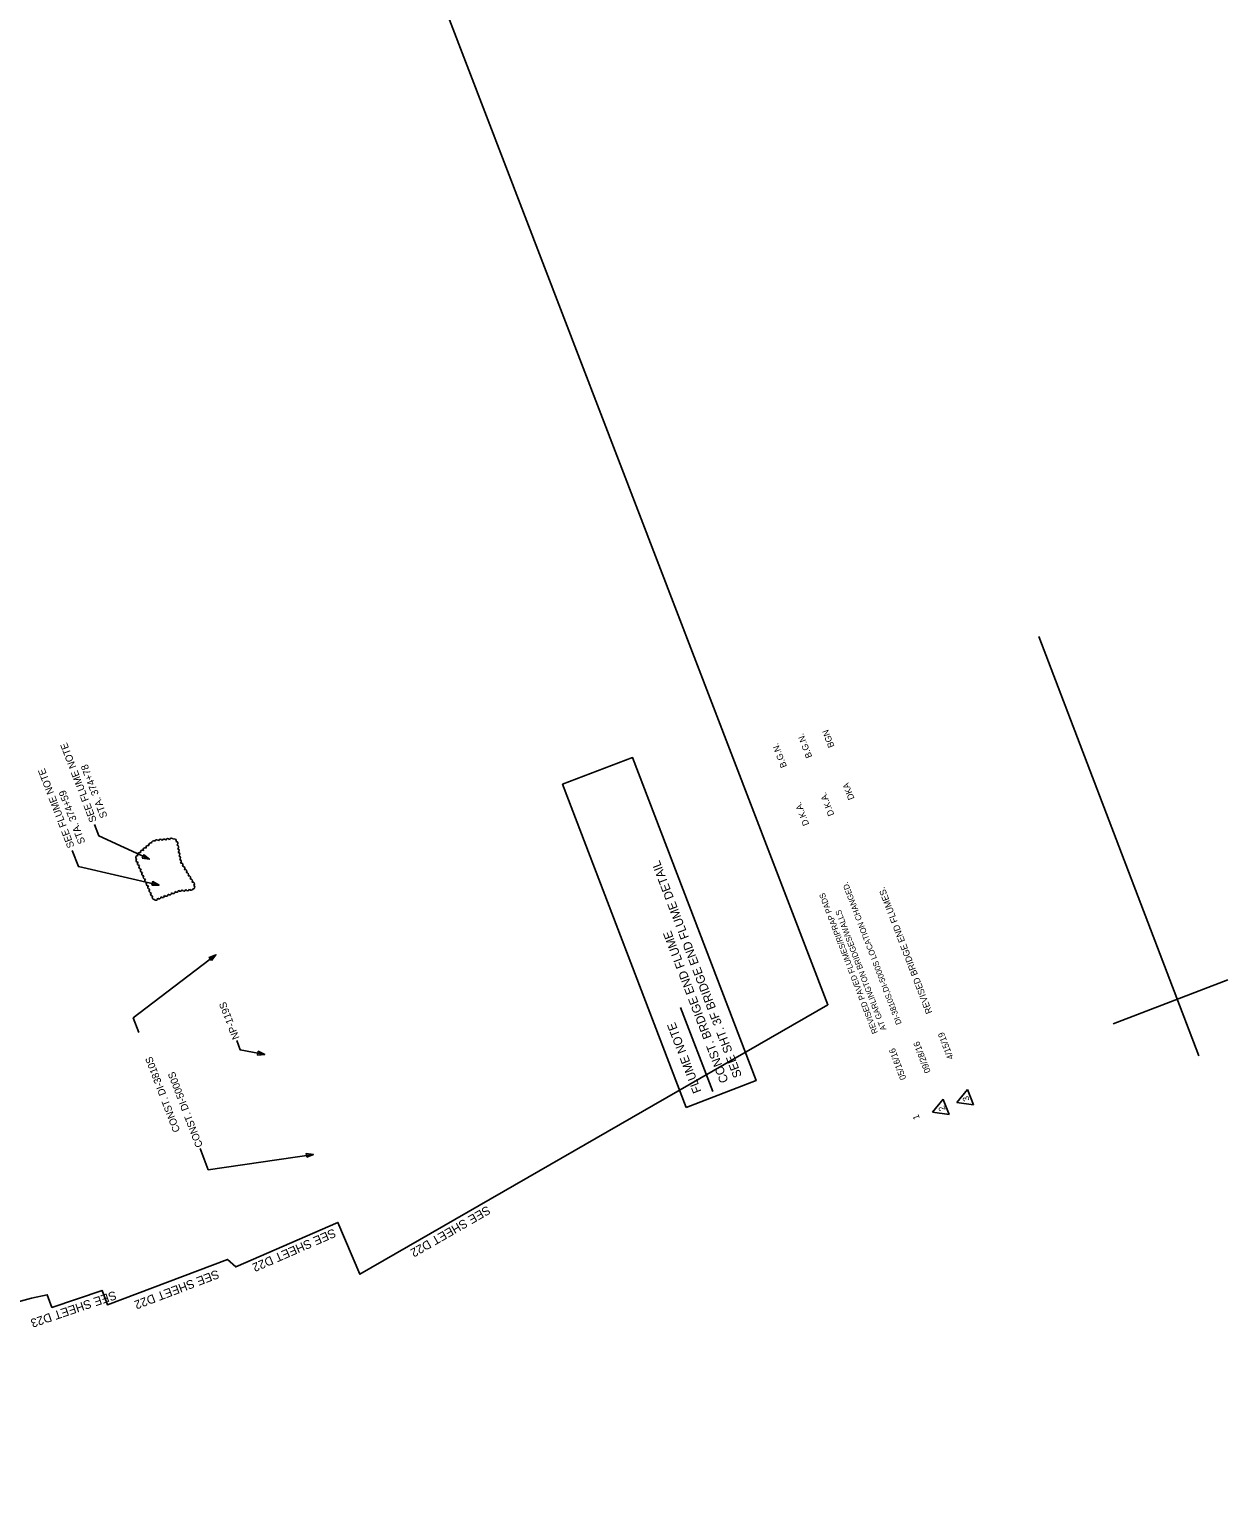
# Model space of a CAD drawing. Extents: x 1611058 to 1612754, y 1091411 to 1093437.
# Drawn here: x 1611925 to 1612754, y 1091411 to 1092422 of the extents above; entities that cross this region are included whole.
import ezdxf

# ---------------------------------------------------------------- set-up
doc = ezdxf.new("R2010")
doc.units = 0
for name, color, linetype in [('BR_CONCRETE', 7, 'Continuous'), ('North Arrow', 7, 'Continuous'), ('RD_HY_Area_XP-Post sub TXT', 7, 'Continuous'), ('RD_HY_Area_XP-Pre sub', 7, 'Continuous'), ('RD_HY_Misc', 7, 'Continuous')]:
    doc.layers.add(name, color=color, linetype=linetype)

msp = doc.modelspace()

# ---------------------------------------------------------------- linework, layer by layer
at = {"layer": 'BR_CONCRETE'}
msp.add_line((1612397.4, 1091687.5), (1612375.2, 1091745.7), dxfattribs=at)
for points in [[(1611969.8, 1091872.1), (1611972.7, 1091864.4), (1612007.7, 1091848.1)], [(1611954.4, 1091854.2), (1611958.6, 1091843.1), (1612014.4, 1091830.3)], [(1612000.5, 1091728.2), (1611996.6, 1091738.4), (1612053.7, 1091782.1)], [(1612068.1, 1091722.8), (1612070.5, 1091716.4), (1612087.5, 1091713.1)], [(1612042.8, 1091648), (1612048.4, 1091633.3), (1612121.2, 1091644)]]:
    msp.add_lwpolyline(points, dxfattribs=at)
for points in [[(1612002.8, 1091849), (1612007.7, 1091848.1), (1612003.9, 1091851.3)], [(1612009.5, 1091830.2), (1612014.4, 1091830.3), (1612010, 1091832.7)], [(1612050.7, 1091778.2), (1612053.7, 1091782.1), (1612049.1, 1091780.2)], [(1612082.5, 1091712.7), (1612087.5, 1091713.1), (1612083, 1091715.3)], [(1612116.6, 1091642.1), (1612121.2, 1091644), (1612116.2, 1091644.6)]]:
    msp.add_lwpolyline(points, close=True, dxfattribs=at)
for centre, start, end in [((1612006.7, 1091856.4), 59.0384, 204.0384), ((1612008.6, 1091858.1), 59.0384, 204.0384), ((1612010.6, 1091859.6), 47.5873, 192.5873), ((1612012.8, 1091860.3), 23.5735, 168.5735), ((1612015.3, 1091860.6), 23.5735, 168.5735), ((1612017.9, 1091860.8), 23.5735, 168.5735), ((1612020.4, 1091861.1), 23.5735, 168.5735), ((1612023, 1091861.4), 23.5735, 168.5735), ((1612025, 1091860.9), 343.5777, 128.5777), ((1612026.1, 1091859.2), 297.3546, 82.3546), ((1612026.6, 1091856.6), 297.3546, 82.3546), ((1611999.7, 1091849.5), 88.2114, 233.2114), ((1611999.8, 1091847.4), 131.0031, 276.0031), ((1612000.9, 1091851.4), 59.0384, 204.0384), ((1612002.9, 1091853.1), 59.0384, 204.0384), ((1612004.8, 1091854.8), 59.0384, 204.0384), ((1612027, 1091854.1), 297.3546, 82.3546), ((1612027.4, 1091851.6), 297.3546, 82.3546), ((1612027.9, 1091849.1), 297.3546, 82.3546), ((1612028.5, 1091846.6), 305.6611, 90.6611), ((1612000.8, 1091845.1), 131.0031, 276.0031), ((1612001.8, 1091842.7), 131.0031, 276.0031), ((1612002.8, 1091840.4), 131.0031, 276.0031), ((1612003.8, 1091838), 131.0031, 276.0031), ((1612029.6, 1091844.2), 318.5086, 103.5086), ((1612030.9, 1091842), 318.5086, 103.5086), ((1612032.2, 1091839.8), 318.5086, 103.5086), ((1612033.5, 1091837.6), 318.5086, 103.5086), ((1612004.8, 1091835.7), 131.0031, 276.0031), ((1612005.9, 1091833.4), 131.0031, 276.0031), ((1612006.9, 1091831), 131.0031, 276.0031), ((1612007.9, 1091828.7), 131.0031, 276.0031), ((1612034.1, 1091827.7), 202.4738, 347.4738), ((1612034.9, 1091835.4), 318.5086, 103.5086), ((1612036.6, 1091828), 202.4738, 347.4738), ((1612036.2, 1091833.2), 318.5086, 103.5086), ((1612037.5, 1091831.1), 318.5086, 103.5086), ((1612037.8, 1091829), 275.4894, 60.4894), ((1612008.9, 1091826.3), 131.0031, 276.0031), ((1612009.9, 1091824), 131.0031, 276.0031), ((1612011, 1091821.6), 131.0031, 276.0031), ((1612012.1, 1091821.1), 218.4145, 3.4145), ((1612014.5, 1091822.1), 218.4145, 3.4145), ((1612016.9, 1091823), 218.4145, 3.4145), ((1612019.3, 1091823.9), 218.4145, 3.4145), ((1612021.7, 1091824.8), 218.4145, 3.4145), ((1612024.1, 1091825.7), 218.4145, 3.4145), ((1612026.5, 1091826.6), 218.4145, 3.4145), ((1612029, 1091827.3), 204.5974, 349.5974), ((1612031.6, 1091827.5), 202.4738, 347.4738)]:
    msp.add_arc(centre, 1.34, start, end, dxfattribs=at)
at = {"layer": 'North Arrow'}
msp.add_lwpolyline([(1612379, 1091676.5), (1612293.6, 1091900), (1612342, 1091918.5), (1612427.4, 1091695)], close=True, dxfattribs=at)
at = {"layer": 'RD_HY_Area_XP-Pre sub'}
for p, q in [((1612622.9, 1092002.3), (1612733.7, 1091712.1)), ((1612753.7, 1091764.7), (1612674.3, 1091734.4)), ((1612573.7, 1091688.8), (1612566.3, 1091679.9)), ((1612577.8, 1091678.2), (1612573.7, 1091688.8)), ((1612556.8, 1091682.1), (1612549.4, 1091673.2)), ((1612556.9, 1091681.9), (1612556.8, 1091682.1)), ((1612560.9, 1091671.5), (1612556.9, 1091681.9)), ((1612566.3, 1091679.9), (1612577.8, 1091678.2)), ((1612549.4, 1091673.2), (1612560.9, 1091671.5))]:
    msp.add_line(p, q, dxfattribs=at)
at = {"layer": 'RD_HY_Misc'}
msp.add_lwpolyline([(1611114.1, 1092647.8), (1611496.9, 1091646.4), (1611649.2, 1091411.3), (1611823.9, 1091453.3), (1611846.4, 1091519), (1611855.6, 1091525.4), (1611926.2, 1091544.6), (1611937.1, 1091546.9), (1611940.3, 1091538.1), (1611975, 1091549.9), (1611978.7, 1091539.9), (1612061.7, 1091571.3), (1612067.6, 1091566.1), (1612138.1, 1091596.9), (1612153.4, 1091561), (1612277.2, 1091632.4), (1612477.1, 1091747.5), (1611951.2, 1093116.5)], dxfattribs=at)
msp.add_lwpolyline([(1611114.1, 1092647.8), (1611496.9, 1091646.4), (1611649.2, 1091411.3), (1611823.9, 1091453.3), (1611846.4, 1091519), (1611855.6, 1091525.4), (1611926.2, 1091544.6), (1611937.1, 1091546.9), (1611940.3, 1091538.1), (1611975, 1091549.9), (1611978.7, 1091539.9), (1612061.7, 1091571.3), (1612067.6, 1091566.1), (1612138.1, 1091596.9), (1612153.4, 1091561), (1612277.2, 1091632.4), (1612477.1, 1091747.5), (1611951.2, 1093116.5)], dxfattribs=at)

# ---------------------------------------------------------------- texts
at = {"layer": 'BR_CONCRETE'}
for s, p in [('SEE FLUME NOTE', (1611971.4, 1091874.8)), ('SEE FLUME NOTE', (1611956, 1091857)), ('STA. 374+78', (1611978.8, 1091877.7)), ('STA. 374+59', (1611963.5, 1091859.8)), ('NP-119S', (1612070.1, 1091724.6)), ('CONST. DI-3810S', (1612029.1, 1091660.4)), ('CONST. DI-5000S', (1612044.8, 1091649.9))]:
    msp.add_text(s, height=5, rotation=110.9145, dxfattribs=at).set_placement(p)
at = {"layer": 'North Arrow'}
for s, p in [('SEE SHT. 3F BRIDGE END FLUME DETAIL', (1612417.7, 1091698.3)), ('CONST. BRDIGE END FLUME', (1612408.4, 1091694.7)), ('FLUME NOTE', (1612389.7, 1091687.6))]:
    msp.add_text(s, height=6, rotation=110.9159, dxfattribs=at).set_placement(p)
at = {"layer": 'RD_HY_Area_XP-Post sub TXT'}
for s, rotation, p in [('SEE SHEET D22', 209.9471, (1612241.4, 1091608.7)), ('SEE SHEET D22', 203.5791, (1612135.1, 1091592.8)), ('SEE SHEET D22', 200.862, (1612054.6, 1091564.3)), ('SEE SHEET D23', 198.8456, (1611983.7, 1091549.7))]:
    msp.add_text(s, height=6, rotation=rotation, dxfattribs=at).set_placement(p)
at = {"layer": 'RD_HY_Area_XP-Pre sub'}
for s, height, rotation, p in [('B.G.N.', 4.4, 110.9145, (1612466.3, 1091919.1)), ('BGN', 4.4, 110.9161, (1612481.7, 1091926.3)), ('B.G.N.', 4.4, 110.9145, (1612448.8, 1091912.4)), ('DKA', 4.4, 110.9161, (1612495.5, 1091890.2)), ('D.K.A.', 4.4, 110.9145, (1612481.6, 1091879)), ('D.K.A.', 4.4, 110.9145, (1612464.2, 1091872.3)), ('DI-3810S,DI-5000S LOCATION CHANGED.', 4, 110.9145, (1612528.2, 1091734.6)), ('REVISED BRIDGE END FLUMES.', 4.5, 110.9161, (1612549.4, 1091742.2)), ('REVISED PAVED FLUMES/RIPRAP PADS', 4, 110.9145, (1612511.7, 1091728.3)), ('AT GARLINGTON BRIDGES/WALLS', 4, 110.9145, (1612517.6, 1091730.5)), ('4/15/19', 4.4, 110.9161, (1612564.1, 1091710.6)), ('05/16/16', 4.4, 110.9145, (1612531.4, 1091696.5)), ('09/28/16', 4.4, 110.9145, (1612548.3, 1091701.2)), ('2', 4.4, 110.9145, (1612558.6, 1091674.9)), ('3', 4.4, 110.9161, (1612575.2, 1091681.7)), ('1', 4.4, 110.9145, (1612540.7, 1091669))]:
    msp.add_text(s, height=height, rotation=rotation, dxfattribs=at).set_placement(p)

doc.saveas('drawing.dxf')
